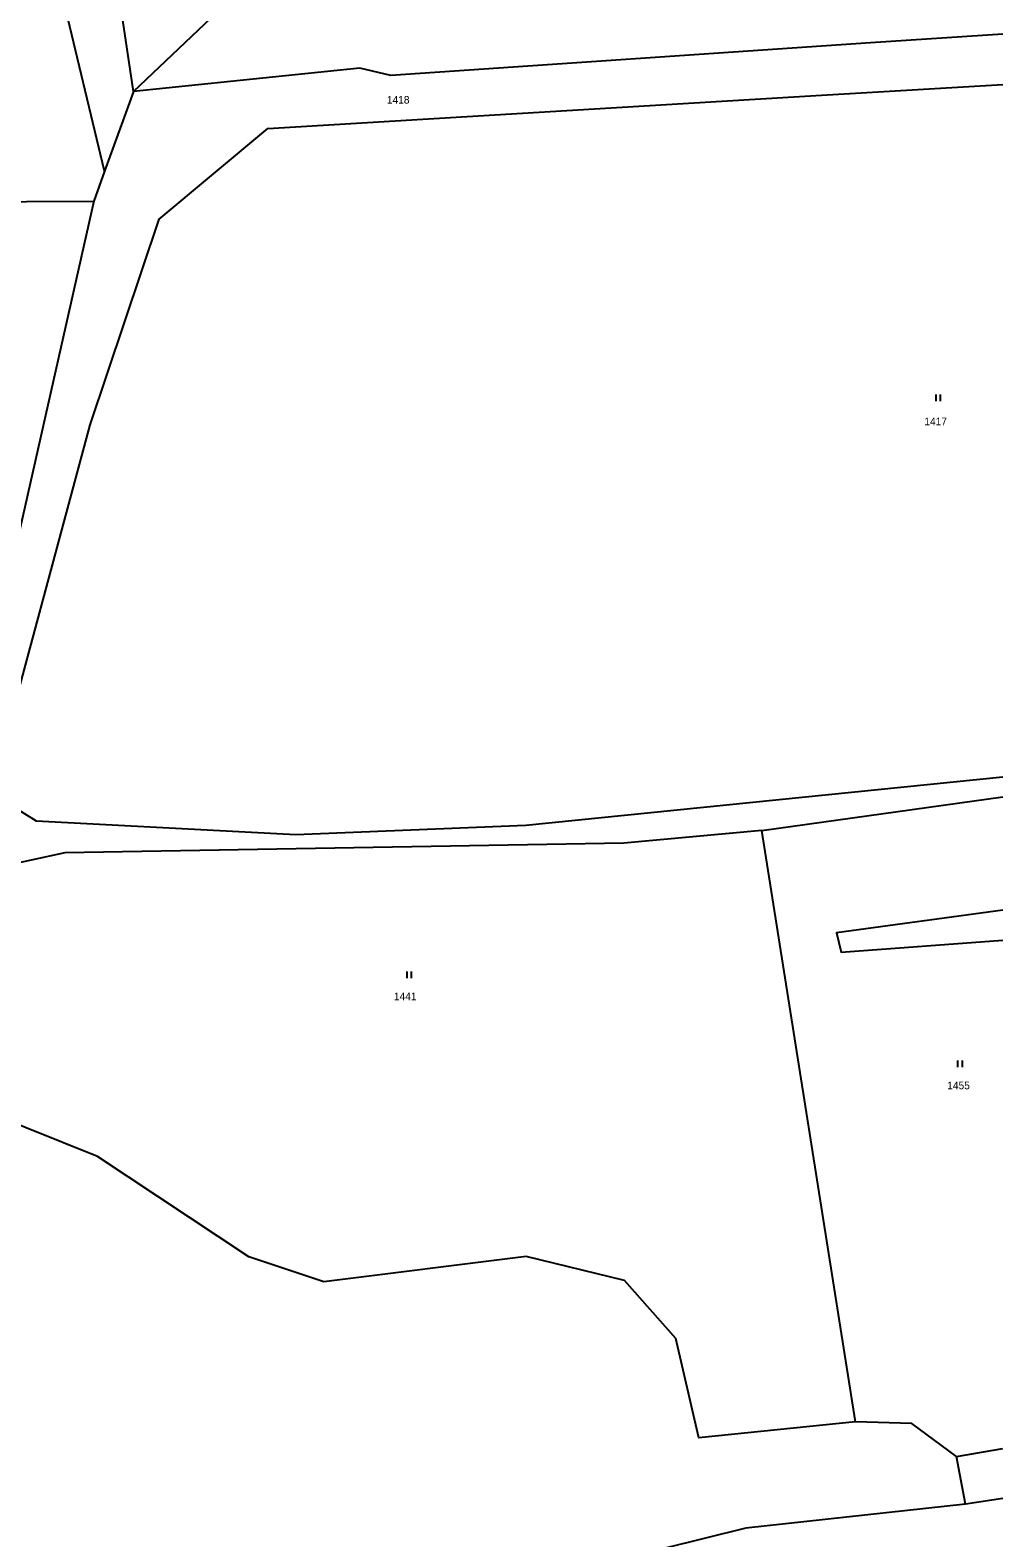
# Model space of a CAD drawing. Extents: x -520431 to -517205, y -1075927 to -1074013.
# Drawn here: x -517422.6 to -517205.1, y -1075574.4 to -1075237.3 of the extents above; entities that cross this region are included whole.
import ezdxf

# ---------------------------------------------------------------- set-up
doc = ezdxf.new("R2010")
doc.units = 0
for name, color, linetype in [('Hranice parcel', 7, 'Continuous'), ('Parcelní čísla', 7, 'Continuous'), ('Značky kultur', 7, 'Continuous')]:
    doc.layers.add(name, color=color, linetype=linetype)

msp = doc.modelspace()

# ---------------------------------------------------------------- linework, layer by layer
at = {"layer": 'Hranice parcel'}
for p, q in [((-517399.41, -1075251.03), (-517405.92, -1075268.88)), ((-517405.92, -1075268.88), (-517408.35, -1075275.53)), ((-517408.35, -1075275.53), (-517426, -1075353.88)), ((-517238.05, -1075548.41), (-517258.99, -1075416.26)), ((-517215.45, -1075556.16), (-517205.09, -1075554.4)), ((-517213.43, -1075566.82), (-517215.45, -1075556.16)), ((-517205.09, -1075565.57), (-517213.43, -1075566.82))]:
    msp.add_line(p, q, dxfattribs=at)
for points in [[(-517399.41, -1075251.03), (-517376.24, -1075228.95), (-517367.55, -1075203.71), (-517365.19, -1075177.56)], [(-517399.41, -1075251.03), (-517406.95, -1075200.67), (-517415.25, -1075180)], [(-517405.92, -1075268.88), (-517415.43, -1075229.31), (-517414.58, -1075200.57), (-517419.1, -1075185.96)], [(-517205.09, -1075238.2), (-517234.71, -1075240.2), (-517341.95, -1075247.45), (-517348.86, -1075245.83), (-517399.41, -1075251.03)], [(-517431.35, -1075407.81), (-517409.11, -1075325.54), (-517393.74, -1075279.61), (-517369.42, -1075259.35), (-517245.65, -1075251.89), (-517205.09, -1075249.45)], [(-517449.04, -1075269.41), (-517438.47, -1075275.74), (-517408.35, -1075275.53)], [(-517431.35, -1075407.81), (-517421.21, -1075414.07), (-517363.14, -1075417.13), (-517311.76, -1075415.03), (-517205.09, -1075404.24)], [(-517258.99, -1075416.26), (-517205.09, -1075408.73)], [(-517258.99, -1075416.26), (-517289.79, -1075419.09), (-517414.79, -1075421.25), (-517429.92, -1075424.54)], [(-517205.09, -1075434.04), (-517242.25, -1075439.13), (-517241.2, -1075443.44), (-517205.09, -1075440.76)], [(-517238.05, -1075548.41), (-517273.05, -1075552.04), (-517278.18, -1075529.84), (-517289.7, -1075516.82), (-517311.68, -1075511.48), (-517356.88, -1075517.13), (-517373.63, -1075511.58), (-517407.49, -1075489.15), (-517431.46, -1075479.51), (-517472.72, -1075475.87)], [(-517215.45, -1075556.16), (-517225.46, -1075548.84), (-517238.05, -1075548.41)], [(-517213.43, -1075566.82), (-517262.53, -1075572.25), (-517308.26, -1075583.54), (-517335.07, -1075579.03), (-517387.45, -1075579.15)]]:
    msp.add_lwpolyline(points, dxfattribs=at)
at = {"layer": 'Značky kultur'}
for p, q in [((-517220.03, -1075320.25), (-517220.03, -1075318.75)), ((-517219.03, -1075320.25), (-517219.03, -1075318.75)), ((-517338.29, -1075449.27), (-517338.29, -1075447.77)), ((-517337.29, -1075449.27), (-517337.29, -1075447.77)), ((-517215.13, -1075469.19), (-517215.13, -1075467.69)), ((-517214.13, -1075469.19), (-517214.13, -1075467.69))]:
    msp.add_line(p, q, dxfattribs=at)

# ---------------------------------------------------------------- texts
at = {"layer": 'Parcelní čísla'}
for s, p in [('1418', (-517342.8, -1075253.75)), ('1417', (-517222.64, -1075325.66)), ('1441', (-517341.23, -1075454.18)), ('1455', (-517217.52, -1075474.1))]:
    msp.add_text(s, height=1.7, dxfattribs=at).set_placement(p)

doc.saveas('drawing.dxf')
